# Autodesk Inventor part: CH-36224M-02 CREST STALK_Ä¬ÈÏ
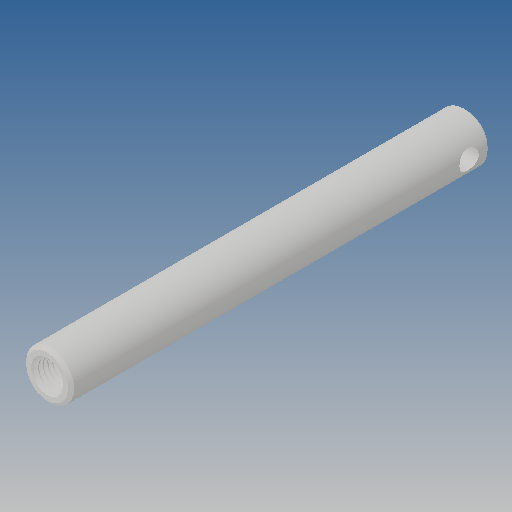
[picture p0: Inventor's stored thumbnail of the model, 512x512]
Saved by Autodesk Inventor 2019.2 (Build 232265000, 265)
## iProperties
Created: 2010-06
Part Number: CH-36224M-02 CREST STALK_Ä¬ÈÏ
Material: Ogólny
Document SubType Name: Modeling
Designer: CADENGINEERING4
Density: 1 g/cm^3
Appearance: Domyślna
Author: CADENGINEERING4
Revision Number: ÈÎºÎ
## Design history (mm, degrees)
feature "NONE"
node "Bryła1"
